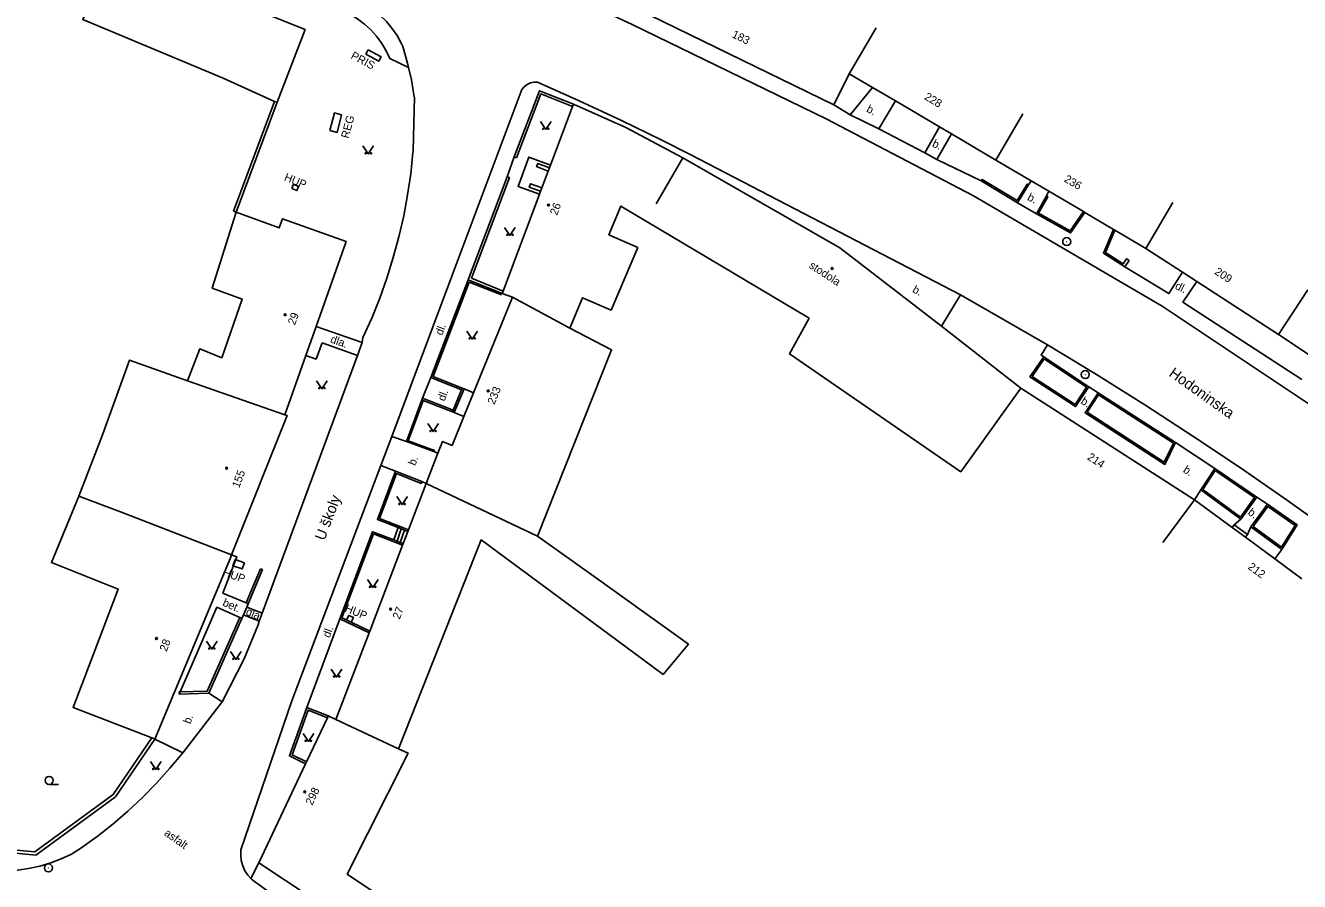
# Model space of a CAD drawing. Extents: x -582162 to -561283, y -1187583 to -1183539.
# Drawn here: x -578409.9 to -578290.5, y -1186104.2 to -1186024 of the extents above; entities that cross this region are included whole.
import ezdxf

# ---------------------------------------------------------------- set-up
doc = ezdxf.new("R2010")
doc.units = 0
for name, color, linetype in [('Vrstva 1', 7, 'Continuous'), ('Vrstva 10', 7, 'Continuous'), ('Vrstva 13', 7, 'Continuous'), ('Vrstva 14', 7, 'Continuous'), ('Vrstva 3', 7, 'Continuous'), ('Vrstva 4', 7, 'Continuous'), ('Vrstva 5', 7, 'Continuous'), ('Vrstva 6', 7, 'Continuous'), ('Vrstva 8', 7, 'Continuous'), ('Vrstva 9', 7, 'Continuous')]:
    doc.layers.add(name, color=color, linetype=linetype)

# ---------------------------------------------------------------- blocks, each defined once
blk = doc.blocks.new('1.079')
at = {"layer": 'Vrstva 1'}
for radius in [0.75, 0.001]:
    blk.add_circle((0, -0.001), radius, dxfattribs=at)
blk = doc.blocks.new('3.040')
at = {"layer": 'Vrstva 1'}
blk.add_line((0, -0.75), (1.75, -0.75), dxfattribs=at)
blk.add_circle((0, 0), 0.75, dxfattribs=at)
blk = doc.blocks.new('3.140')
at = {"layer": 'Vrstva 1'}
blk.add_lwpolyline([(-1, 1.5), (0, 0), (1, 1.5)], dxfattribs=at)
for centre in [(-0.5, 0.1), (0.5, 0.1)]:
    blk.add_circle(centre, 0.1, dxfattribs=at)
blk = doc.blocks.new('4.020')
at = {"layer": 'Vrstva 1'}
blk.add_circle((0, 0), 0.175, dxfattribs=at)

msp = doc.modelspace()

# ---------------------------------------------------------------- linework, layer by layer
at = {"layer": 'Vrstva 10'}
for points in [[(-578427.88, -1186000), (-578418.8, -1186004.29), (-578405.43, -1186010.15), (-578378.73, -1186021.68), (-578378, -1186022.06), (-578377.31, -1186022.51), (-578376.67, -1186023.02), (-578376.07, -1186023.6), (-578375.54, -1186024.23), (-578375.07, -1186024.91), (-578374.67, -1186025.63), (-578374.51, -1186025.97), (-578374.08, -1186027.52), (-578373.98, -1186027.94)], [(-578366.96, -1186000), (-578371.51, -1186010.78), (-578371.68, -1186011.05), (-578371.9, -1186011.53), (-578372.06, -1186012.04), (-578372.13, -1186012.57), (-578372.12, -1186013.1), (-578372.06, -1186013.41), (-578371.89, -1186013.94), (-578371.65, -1186014.44), (-578371.34, -1186014.9), (-578370.97, -1186015.31), (-578370.54, -1186015.67), (-578370.06, -1186015.96), (-578369.55, -1186016.18), (-578353.03, -1186023.9), (-578334.84, -1186032.75), (-578321.02, -1186039.95), (-578303.35, -1186050.31), (-578281.8, -1186064.68)], [(-578400.4, -1186013.8), (-578379.23, -1186023.07), (-578378.76, -1186023.37), (-578378.11, -1186023.85), (-578377.52, -1186024.4), (-578376.98, -1186025), (-578376.5, -1186025.66), (-578376.09, -1186026.36), (-578375.75, -1186027.09), (-578373.98, -1186027.94)], [(-578377.78, -1186026.28), (-578376.57, -1186026.93), (-578376.78, -1186027.33), (-578377.99, -1186026.68), (-578377.78, -1186026.28)], [(-578373.98, -1186027.94), (-578373.72, -1186029.08), (-578373.45, -1186030.67), (-578373.44, -1186030.72), (-578373.56, -1186035.66), (-578373.58, -1186035.88), (-578373.79, -1186037.88), (-578374.08, -1186039.86), (-578374.44, -1186041.84), (-578374.89, -1186043.8), (-578375.42, -1186045.74), (-578376.02, -1186047.66), (-578376.69, -1186049.55), (-578377.44, -1186051.42), (-578378.27, -1186053.25), (-578378.34, -1186053.71)], [(-578369.84, -1186047.25), (-578363.37, -1186030), (-578363.16, -1186029.73), (-578362.88, -1186029.52), (-578362.57, -1186029.37), (-578362.23, -1186029.3), (-578361.91, -1186029.31), (-578357.99, -1186031.04), (-578354.1, -1186032.85), (-578350.24, -1186034.73), (-578347.52, -1186036.11), (-578322.24, -1186049.25)], [(-578332.58, -1186032.35), (-578330.49, -1186029.81)], [(-578332.58, -1186032.35), (-578334.11, -1186031.42)], [(-578329.92, -1186033.67), (-578328.36, -1186031.06)], [(-578381.37, -1186033.84), (-578380.93, -1186032.19), (-578380.26, -1186032.37), (-578380.69, -1186034.02), (-578381.37, -1186033.84)], [(-578329.92, -1186033.67), (-578332.58, -1186032.35)], [(-578325.61, -1186035.92), (-578329.92, -1186033.67)], [(-578325.61, -1186035.92), (-578324.22, -1186033.49)], [(-578324.47, -1186036.54), (-578323.1, -1186034.15)], [(-578364.75, -1186038.17), (-578364.09, -1186036.31)], [(-578360.68, -1186037.08), (-578362.71, -1186036.33), (-578363.72, -1186039.07), (-578361.71, -1186039.81)], [(-578324.47, -1186036.54), (-578325.61, -1186035.92)], [(-578320.3, -1186038.55), (-578324.47, -1186036.54)], [(-578315.87, -1186038.92), (-578315.64, -1186038.54)], [(-578384.93, -1186039.26), (-578384.77, -1186038.87), (-578384.29, -1186039.07), (-578384.45, -1186039.47), (-578384.93, -1186039.26)], [(-578314.2, -1186039.97), (-578313.96, -1186039.53)], [(-578315.13, -1186041.63), (-578316.9, -1186040.6)], [(-578301.44, -1186047.12), (-578302.71, -1186049.12), (-578306.85, -1186046.61)], [(-578375.57, -1186062.52), (-578369.84, -1186047.25)], [(-578290.27, -1186057.18), (-578301.4, -1186049.93), (-578300.11, -1186047.98)], [(-578322.24, -1186049.25), (-578324.04, -1186052.18)], [(-578322.24, -1186049.25), (-578314.11, -1186053.93)], [(-578378.34, -1186053.71), (-578382.66, -1186052.2)], [(-578382.09, -1186053.75), (-578382.66, -1186055.26), (-578383.62, -1186054.92)], [(-578378.76, -1186054.94), (-578382.09, -1186053.75)], [(-578378.76, -1186054.94), (-578378.34, -1186053.71)], [(-578314.11, -1186053.93), (-578314.7, -1186054.88), (-578314.45, -1186055.05)], [(-578314.11, -1186053.93), (-578309.52, -1186056.71), (-578304.98, -1186059.56), (-578300.48, -1186062.48), (-578296.02, -1186065.46), (-578291.61, -1186068.51), (-578287.24, -1186071.63)], [(-578378.76, -1186054.94), (-578387.7, -1186079.07)], [(-578371.91, -1186056.98), (-578372.68, -1186058.94)], [(-578310.23, -1186057.86), (-578309.36, -1186058.41)], [(-578368.95, -1186057.99), (-578369.02, -1186058.15)], [(-578368.79, -1186058.06), (-578367.9, -1186058.42)], [(-578369.8, -1186060.06), (-578369.86, -1186060.22)], [(-578369.7, -1186060.28), (-578368.8, -1186060.63)], [(-578375.57, -1186062.52), (-578376.59, -1186065.23)], [(-578374.18, -1186062.98), (-578375.57, -1186062.52)], [(-578302.11, -1186063.09), (-578298.41, -1186065.51)], [(-578371.62, -1186063.94), (-578371.24, -1186064.09)], [(-578376.59, -1186065.23), (-578384.92, -1186087.3), (-578389.7, -1186101.26), (-578389.72, -1186101.77), (-578389.67, -1186102.27), (-578389.53, -1186102.76), (-578389.32, -1186103.23), (-578389.04, -1186103.65), (-578388.77, -1186103.95)], [(-578375.21, -1186065.78), (-578376.59, -1186065.23)], [(-578372.75, -1186066.75), (-578372.35, -1186066.94)], [(-578300.31, -1186068.45), (-578299.73, -1186067.52)], [(-578294.47, -1186068.21), (-578293.48, -1186068.87)], [(-578374.97, -1186071.06), (-578375.37, -1186072.22)], [(-578296.78, -1186071.05), (-578296.59, -1186070.8)], [(-578295.98, -1186070.28), (-578296.59, -1186070.8)], [(-578296.59, -1186070.8), (-578295.34, -1186071.72)], [(-578295.34, -1186071.72), (-578295.04, -1186070.99)], [(-578374.67, -1186071.18), (-578375.07, -1186072.33)], [(-578374.37, -1186071.3), (-578374.77, -1186072.45)], [(-578295.53, -1186071.97), (-578295.34, -1186071.72)], [(-578292.78, -1186073.99), (-578292.13, -1186073.12)], [(-578389.2, -1186078.12), (-578391.39, -1186077.21), (-578390.08, -1186073.8), (-578390.57, -1186073.62)], [(-578390.25, -1186074.05), (-578390.47, -1186074.63), (-578389.59, -1186074.93), (-578389.38, -1186074.37)], [(-578389.14, -1186078.51), (-578389.02, -1186078.2)], [(-578395.48, -1186086.67), (-578391.95, -1186078.53), (-578389.79, -1186079.48)], [(-578389.61, -1186079.57), (-578389.45, -1186079.25)], [(-578389.45, -1186079.25), (-578389.14, -1186078.51)], [(-578387.99, -1186079.84), (-578389.45, -1186079.25)], [(-578389.14, -1186078.51), (-578387.7, -1186079.07)], [(-578387.99, -1186079.84), (-578387.7, -1186079.07)], [(-578379.81, -1186079.72), (-578379.6, -1186079.29), (-578379.16, -1186079.48), (-578379.37, -1186079.93)], [(-578388.1, -1186080.17), (-578389.41, -1186083.36), (-578391.46, -1186087.39)], [(-578387.99, -1186079.84), (-578388.1, -1186080.17)], [(-578380.43, -1186079.6), (-578383.51, -1186087.91)], [(-578391.46, -1186087.39), (-578392.72, -1186086.58)], [(-578391.46, -1186087.39), (-578395.15, -1186092.18)], [(-578397.78, -1186090.88), (-578395.15, -1186092.18)], [(-578395.15, -1186092.18), (-578396.35, -1186093.62), (-578397.61, -1186095.01), (-578398.92, -1186096.35), (-578400.29, -1186097.63), (-578401.72, -1186098.85), (-578403.19, -1186100.01), (-578404.72, -1186101.1), (-578405.57, -1186101.67), (-578406.54, -1186102.12), (-578407.53, -1186102.49), (-578408.55, -1186102.79), (-578409.6, -1186103.01), (-578410.65, -1186103.16), (-578411.71, -1186103.22), (-578412.78, -1186103.2), (-578413.14, -1186103.18), (-578421.34, -1186101.44)], [(-578388.03, -1186102.49), (-578388.77, -1186103.95)], [(-578388.77, -1186103.95), (-578388.7, -1186104.02), (-578388.3, -1186104.34), (-578388.11, -1186104.46), (-578381.6, -1186109.24), (-578372.12, -1186115.87)]]:
    msp.add_lwpolyline(points, dxfattribs=at)
at = {"layer": 'Vrstva 4'}
for points in [[(-578386.3, -1186031.19), (-578383.69, -1186024.36), (-578391.05, -1186021.39)], [(-578351.37, -1186023.01), (-578334.11, -1186031.42)], [(-578330.17, -1186024.2), (-578332.7, -1186028.51)], [(-578334.11, -1186031.42), (-578332.7, -1186028.51)], [(-578332.7, -1186028.51), (-578330.49, -1186029.81)], [(-578330.49, -1186029.81), (-578328.36, -1186031.06)], [(-578386.54, -1186031.1), (-578386.3, -1186031.19)], [(-578360.68, -1186037.08), (-578358.61, -1186031.57)], [(-578358.61, -1186031.57), (-578358.53, -1186031.36)], [(-578358.53, -1186031.36), (-578353.61, -1186033.54), (-578348.28, -1186036.38)], [(-578328.36, -1186031.06), (-578324.22, -1186033.49)], [(-578316.4, -1186032.28), (-578318.93, -1186036.6)], [(-578324.22, -1186033.49), (-578323.1, -1186034.15)], [(-578323.1, -1186034.15), (-578318.93, -1186036.6)], [(-578350.77, -1186040.72), (-578348.28, -1186036.38)], [(-578348.28, -1186036.38), (-578333.57, -1186044.84), (-578324.04, -1186052.18)], [(-578361.49, -1186039.22), (-578360.89, -1186037.63)], [(-578360.89, -1186037.63), (-578360.77, -1186037.32)], [(-578360.77, -1186037.32), (-578360.68, -1186037.08)], [(-578318.93, -1186036.6), (-578315.64, -1186038.54)], [(-578315.64, -1186038.54), (-578313.96, -1186039.53)], [(-578365.13, -1186048.88), (-578361.71, -1186039.81)], [(-578361.71, -1186039.81), (-578361.61, -1186039.53)], [(-578361.61, -1186039.53), (-578361.49, -1186039.22)], [(-578313.96, -1186039.53), (-578310.72, -1186041.44)], [(-578302.35, -1186040.58), (-578304.89, -1186044.88)], [(-578390.15, -1186041.48), (-578386.11, -1186042.96), (-578385.81, -1186042.11), (-578379.84, -1186044.25), (-578382.66, -1186052.2), (-578383.62, -1186054.92), (-578385.6, -1186060.49)], [(-578310.72, -1186041.44), (-578310.6, -1186041.51)], [(-578310.6, -1186041.51), (-578307.91, -1186043.1)], [(-578307.91, -1186043.1), (-578307.78, -1186043.18)], [(-578307.78, -1186043.18), (-578304.89, -1186044.88)], [(-578304.89, -1186044.88), (-578301.44, -1186047.12)], [(-578301.44, -1186047.12), (-578300.11, -1186047.98)], [(-578300.11, -1186047.98), (-578292.43, -1186052.97)], [(-578367.9, -1186058.42), (-578364.25, -1186049.46)], [(-578365.21, -1186049.1), (-578365.13, -1186048.88)], [(-578364.25, -1186049.46), (-578365.21, -1186049.1)], [(-578289.71, -1186048.77), (-578292.43, -1186052.97)], [(-578324.04, -1186052.18), (-578316.61, -1186057.99)], [(-578292.43, -1186052.97), (-578289.02, -1186055.23)], [(-578368.8, -1186060.63), (-578367.9, -1186058.42)], [(-578316.61, -1186057.99), (-578300.31, -1186068.45)], [(-578390.57, -1186073.62), (-578385.38, -1186060.54), (-578385.6, -1186060.49)], [(-578371.24, -1186064.09), (-578370.81, -1186063), (-578369.91, -1186063.36), (-578368.8, -1186060.63)], [(-578372.35, -1186066.94), (-578371.24, -1186064.09)], [(-578374, -1186071.27), (-578372.35, -1186066.94)], [(-578303.28, -1186072.47), (-578300.31, -1186068.45)], [(-578300.31, -1186068.45), (-578296.78, -1186071.05)], [(-578296.78, -1186071.05), (-578295.53, -1186071.97)], [(-578374.49, -1186072.55), (-578374.06, -1186071.42)], [(-578374.06, -1186071.42), (-578374, -1186071.27)], [(-578295.53, -1186071.97), (-578292.78, -1186073.99)], [(-578377.63, -1186080.77), (-578374.55, -1186072.7)], [(-578374.55, -1186072.7), (-578374.49, -1186072.55)], [(-578390.68, -1186073.89), (-578397.78, -1186090.88)], [(-578390.57, -1186073.62), (-578390.68, -1186073.89)], [(-578292.78, -1186073.99), (-578290.25, -1186075.85)], [(-578380.8, -1186089.04), (-578377.69, -1186080.92)], [(-578377.69, -1186080.92), (-578377.63, -1186080.77)], [(-578383.56, -1186093.03), (-578381.6, -1186088.88)], [(-578381.6, -1186088.88), (-578381.52, -1186088.7)], [(-578381.52, -1186088.7), (-578380.8, -1186089.04)], [(-578397.78, -1186090.88), (-578398.06, -1186090.76)], [(-578388.03, -1186102.49), (-578383.65, -1186093.22)], [(-578383.65, -1186093.22), (-578383.56, -1186093.03)], [(-578372.48, -1186114.35), (-578381.2, -1186108.51), (-578380.61, -1186107.4), (-578388.03, -1186102.49)]]:
    msp.add_lwpolyline(points, dxfattribs=at)
at = {"layer": 'Vrstva 5'}
for points in [[(-578386.54, -1186031.1), (-578391.38, -1186028.92), (-578404.52, -1186023.44), (-578401.74, -1186017.08)], [(-578316.61, -1186057.99), (-578322.23, -1186065.83), (-578338.27, -1186054.77), (-578336.45, -1186051.43), (-578354.1, -1186040.92), (-578355.21, -1186043.6), (-578352.5, -1186044.8), (-578355.01, -1186050.67), (-578357.67, -1186049.51), (-578358.86, -1186052.37)], [(-578394.7, -1186057.29), (-578393.56, -1186054.31), (-578391.5, -1186055.14), (-578389.57, -1186049.63), (-578392.39, -1186048.6), (-578390.15, -1186041.48)], [(-578358.86, -1186052.37), (-578364.25, -1186049.46)], [(-578358.86, -1186052.37), (-578354.95, -1186054.39), (-578361.89, -1186071.86)], [(-578404.89, -1186068.12), (-578402.69, -1186062.37), (-578400.15, -1186055.37), (-578394.7, -1186057.29)], [(-578394.7, -1186057.29), (-578385.6, -1186060.49)], [(-578361.89, -1186071.86), (-578372.35, -1186066.94)], [(-578398.06, -1186090.76), (-578405.43, -1186087.91), (-578401.21, -1186076.82), (-578407.46, -1186074.32), (-578404.89, -1186068.12)], [(-578404.89, -1186068.12), (-578400.98, -1186069.58), (-578390.57, -1186073.62)], [(-578361.89, -1186071.86), (-578356.37, -1186075.81), (-578347.75, -1186081.99), (-578350.13, -1186084.82), (-578352.2, -1186083.29), (-578367.17, -1186072.2), (-578374.93, -1186091.79)], [(-578374.93, -1186091.79), (-578380.8, -1186089.04)], [(-578374.93, -1186091.79), (-578374.04, -1186092.2), (-578379.75, -1186103.55), (-578369.66, -1186110.31)]]:
    msp.add_lwpolyline(points, dxfattribs=at)
at = {"layer": 'Vrstva 9'}
for points in [[(-578364.09, -1186036.31), (-578361.71, -1186030.1), (-578358.53, -1186031.36)], [(-578358.61, -1186031.57), (-578361.58, -1186030.4), (-578363.88, -1186036.39)], [(-578390.15, -1186041.48), (-578390.39, -1186041.39), (-578386.54, -1186031.1)], [(-578390.15, -1186041.48), (-578386.3, -1186031.19)], [(-578364.09, -1186036.31), (-578363.88, -1186036.39)], [(-578360.77, -1186037.32), (-578361.87, -1186036.91), (-578361.98, -1186037.22), (-578360.89, -1186037.63)], [(-578364.75, -1186038.17), (-578368.4, -1186047.82)], [(-578364.54, -1186038.25), (-578368.1, -1186047.69)], [(-578364.75, -1186038.17), (-578364.54, -1186038.25)], [(-578361.61, -1186039.53), (-578362.68, -1186039.14), (-578362.57, -1186038.83), (-578361.49, -1186039.22)], [(-578320.3, -1186038.55), (-578320.23, -1186038.43), (-578316.95, -1186040.39), (-578316, -1186038.85), (-578315.87, -1186038.92)], [(-578316.9, -1186040.6), (-578320.3, -1186038.55)], [(-578316.9, -1186040.6), (-578315.87, -1186038.92)], [(-578315.13, -1186041.63), (-578314.2, -1186039.97)], [(-578310.72, -1186041.44), (-578311.98, -1186043.24), (-578314.93, -1186041.57), (-578314.07, -1186040.04), (-578314.2, -1186039.97)], [(-578310.6, -1186041.51), (-578311.94, -1186043.44), (-578315.13, -1186041.63)], [(-578306.85, -1186046.61), (-578308.86, -1186045.32), (-578307.91, -1186043.1)], [(-578306.85, -1186046.61), (-578306.45, -1186046.02), (-578306.68, -1186045.86), (-578307, -1186046.33), (-578308.67, -1186045.26), (-578307.78, -1186043.18)], [(-578368.4, -1186047.82), (-578371.91, -1186056.98)], [(-578365.27, -1186049.25), (-578368.3, -1186048.05), (-578371.69, -1186056.89), (-578368.95, -1186057.99)], [(-578365.21, -1186049.1), (-578368.4, -1186047.82)], [(-578368.1, -1186047.69), (-578365.13, -1186048.88)], [(-578314.45, -1186055.05), (-578315.74, -1186056.94), (-578311.47, -1186059.72), (-578310.23, -1186057.86)], [(-578314.41, -1186055.25), (-578315.53, -1186056.9), (-578311.51, -1186059.51), (-578310.44, -1186057.9), (-578314.41, -1186055.25)], [(-578310.23, -1186057.86), (-578314.45, -1186055.05)], [(-578371.91, -1186056.98), (-578369.02, -1186058.15)], [(-578372.68, -1186058.94), (-578374.18, -1186062.98)], [(-578372.68, -1186058.94), (-578369.8, -1186060.06)], [(-578369.02, -1186058.15), (-578369.8, -1186060.06)], [(-578368.79, -1186058.06), (-578369.7, -1186060.28)], [(-578368.95, -1186057.99), (-578368.79, -1186058.06)], [(-578302.11, -1186063.09), (-578303.09, -1186065.13), (-578310.58, -1186060.3), (-578309.36, -1186058.41)], [(-578310.38, -1186060.25), (-578309.32, -1186058.62), (-578302.3, -1186063.15), (-578303.15, -1186064.91), (-578310.38, -1186060.25)], [(-578309.36, -1186058.41), (-578302.11, -1186063.09)], [(-578371.62, -1186063.94), (-578371.57, -1186063.83), (-578374.02, -1186062.91), (-578372.62, -1186059.15), (-578369.86, -1186060.22)], [(-578369.86, -1186060.22), (-578369.7, -1186060.28)], [(-578374.18, -1186062.98), (-578371.62, -1186063.94)], [(-578375.21, -1186065.78), (-578376.91, -1186070.29), (-578374.97, -1186071.06)], [(-578374, -1186071.27), (-578376.71, -1186070.2), (-578375.12, -1186065.99), (-578372.82, -1186066.92), (-578372.75, -1186066.75)], [(-578372.75, -1186066.75), (-578375.21, -1186065.78)], [(-578298.41, -1186065.51), (-578299.73, -1186067.52)], [(-578298.37, -1186065.72), (-578299.53, -1186067.48), (-578296.01, -1186070.07), (-578294.68, -1186068.24), (-578298.37, -1186065.72)], [(-578294.47, -1186068.21), (-578298.41, -1186065.51)], [(-578299.73, -1186067.52), (-578295.98, -1186070.28)], [(-578295.98, -1186070.28), (-578294.47, -1186068.21)], [(-578295.04, -1186070.99), (-578293.48, -1186068.87)], [(-578294.82, -1186070.95), (-578293.44, -1186069.08), (-578290.89, -1186070.85), (-578292.17, -1186072.9), (-578294.82, -1186070.95)], [(-578293.48, -1186068.87), (-578290.68, -1186070.81), (-578292.13, -1186073.12)], [(-578374.97, -1186071.06), (-578374.67, -1186071.18)], [(-578292.13, -1186073.12), (-578295.04, -1186070.99)], [(-578375.37, -1186072.22), (-578377.37, -1186071.45), (-578380.43, -1186079.6)], [(-578379.81, -1186079.72), (-578380.23, -1186079.52), (-578377.28, -1186071.65), (-578374.55, -1186072.7)], [(-578375.07, -1186072.33), (-578375.37, -1186072.22)], [(-578374.67, -1186071.18), (-578374.37, -1186071.3)], [(-578374.37, -1186071.3), (-578374.06, -1186071.42)], [(-578374.77, -1186072.45), (-578375.07, -1186072.33)], [(-578374.49, -1186072.55), (-578374.77, -1186072.45)], [(-578389.38, -1186074.37), (-578390.25, -1186074.05)], [(-578389.02, -1186078.2), (-578389.2, -1186078.12), (-578387.87, -1186074.92)], [(-578389.02, -1186078.2), (-578387.69, -1186074.99)], [(-578387.69, -1186074.99), (-578387.87, -1186074.92)], [(-578389.61, -1186079.57), (-578389.79, -1186079.48), (-578392.85, -1186086.38), (-578395.49, -1186086.47), (-578395.48, -1186086.67), (-578392.72, -1186086.58), (-578389.61, -1186079.57)], [(-578377.69, -1186080.92), (-578380.43, -1186079.6)], [(-578379.37, -1186079.93), (-578379.81, -1186079.72)], [(-578377.63, -1186080.77), (-578379.37, -1186079.93)], [(-578383.51, -1186087.91), (-578385.15, -1186092.47), (-578383.65, -1186093.22)], [(-578383.56, -1186093.03), (-578384.9, -1186092.37), (-578383.4, -1186088.17), (-578381.6, -1186088.88)], [(-578383.51, -1186087.91), (-578381.52, -1186088.7)], [(-578414.87, -1186100.86), (-578414.81, -1186100.56), (-578411.76, -1186101.2), (-578409.02, -1186101.46), (-578401.68, -1186096.09), (-578398.06, -1186090.76)], [(-578414.87, -1186100.86), (-578411.8, -1186101.5), (-578408.93, -1186101.77), (-578401.46, -1186096.31), (-578397.78, -1186090.88)]]:
    msp.add_lwpolyline(points, dxfattribs=at)

# ---------------------------------------------------------------- block references
at = {"layer": 'Vrstva 1', "xscale": 0.5, "yscale": 0.5}
for p in [(-578312.3, -1186044.25), (-578310.56, -1186056.71), (-578407.74, -1186102.96)]:
    msp.add_blockref('1.079', p, dxfattribs=at)
at = {"layer": 'Vrstva 3', "xscale": 0.5, "yscale": 0.5}
for name, p in [('3.140', (-578361.13, -1186033.73)), ('3.140', (-578377.76, -1186036.02)), ('3.140', (-578364.48, -1186043.66)), ('3.140', (-578368.02, -1186053.38)), ('3.140', (-578382.11, -1186058.04)), ('3.140', (-578371.69, -1186062.06)), ('3.140', (-578374.6, -1186068.9)), ('3.140', (-578377.35, -1186076.66)), ('3.140', (-578392.43, -1186082.45)), ('3.140', (-578390.17, -1186083.42)), ('3.140', (-578380.73, -1186085.07)), ('3.140', (-578383.38, -1186091.1)), ('3.140', (-578397.68, -1186093.74)), ('3.040', (-578407.68, -1186094.76))]:
    msp.add_blockref(name, p, dxfattribs=at)
at = {"layer": 'Vrstva 8'}
for p, xscale, yscale, rotation in [((-578360.87, -1186040.82), 0.49999999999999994, 0.5000000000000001, -110.66003145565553), ((-578385.56, -1186051.1), 0.5, 0.5000000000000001, 24.20998393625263), ((-578375.67, -1186078.7), 0.5, 0.5, 69.04018373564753), ((-578397.62, -1186081.45), 0.5, 0.5, 67.31983723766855)]:
    msp.add_blockref('4.020', p, dxfattribs=dict(at, xscale=xscale, yscale=yscale, rotation=rotation))
at = {"layer": 'Vrstva 8', "xscale": 0.5, "yscale": 0.5}
for p in [(-578334.29, -1186046.76), (-578366.52, -1186058.25), (-578391.04, -1186065.49), (-578383.72, -1186095.84)]:
    msp.add_blockref('4.020', p, dxfattribs=at)

# ---------------------------------------------------------------- texts
at = {"layer": 'Vrstva 13'}
for s, rotation, p in [('Hodoninska', 324.57, (-578302.79, -1186056.79)), ('U školy', 69.32, (-578381.87, -1186072.34))]:
    msp.add_text(s, height=1, rotation=rotation, dxfattribs=at).set_placement(p)
at = {"layer": 'Vrstva 14'}
for s, rotation, p in [('PRIS', 331.957, (-578379.47, -1186027.04)), ('b.', 333.667, (-578331.13, -1186032.05)), ('REG', 75.149, (-578379.61, -1186034.62)), ('b.', 333.667, (-578324.97, -1186035.3)), ('HUP', 337.279, (-578385.71, -1186038.48)), ('b.', 333.667, (-578316.05, -1186040.33)), ('stodola', 326.91, (-578336.51, -1186046.66)), ('b.', 332.54, (-578326.82, -1186048.96)), ('dl.', 333.667, (-578302.21, -1186048.64)), ('dla.', 340.34, (-578381.38, -1186053.69)), ('dl.', 69.338, (-578370.83, -1186053.09)), ('dl.', 69.338, (-578370.61, -1186059.26)), ('b.', 326.832, (-578311.05, -1186059.38)), ('b.', 69.338, (-578373.36, -1186065.3)), ('b.', 326.832, (-578301.45, -1186065.81)), ('b.', 321.646, (-578295.39, -1186069.75)), ('HUP', 341.154, (-578391.46, -1186075.56)), ('bet.', 336.26, (-578391.49, -1186078.35)), ('HUP', 337.471, (-578380.02, -1186078.9)), ('dla.', 338, (-578389.31, -1186079.22)), ('dl.', 69.338, (-578381.39, -1186081.44)), ('b.', 69.338, (-578394.45, -1186089.52)), ('asfalt', 324.655, (-578396.96, -1186099.85))]:
    msp.add_text(s, height=0.75, rotation=rotation, dxfattribs=at).set_placement(p)
at = {"layer": 'Vrstva 6'}
for s, rotation, p in [('183', 334.022, (-578343.74, -1186025.06)), ('228', 329.588, (-578325.71, -1186030.87)), ('236', 329.449, (-578312.61, -1186038.58)), ('26', 69.353, (-578360.07, -1186041.83)), ('209', 327.014, (-578298.5, -1186047.24)), ('29', 69.266, (-578384.64, -1186052.12)), ('233', 67.826, (-578365.94, -1186059.58)), ('214', 327.312, (-578310.44, -1186064.62)), ('155', 69.266, (-578389.87, -1186067.4)), ('212', 323.663, (-578295.38, -1186074.87)), ('27', 69.078, (-578374.82, -1186079.71)), ('28', 69.266, (-578396.66, -1186082.73)), ('298', 64.717, (-578383.02, -1186097.15))]:
    msp.add_text(s, height=0.75, rotation=rotation, dxfattribs=at).set_placement(p)

doc.saveas('drawing.dxf')
